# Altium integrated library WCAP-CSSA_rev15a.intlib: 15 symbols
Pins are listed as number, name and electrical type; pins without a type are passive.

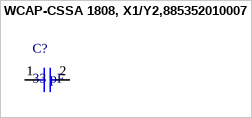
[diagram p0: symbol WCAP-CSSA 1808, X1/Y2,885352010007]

## WCAP-CSSA 1808, X1/Y2,885352010007
designator C?, comment 33 pF
WCAP-CSSA MLCC, NP0, 1808,X1/Y2, 33 pF,250Vac; Manufacturer: Wurth Elektronik; partNo: 885352010007; E-mail: libraries@we-online.com
footprint WCAP-CSSA 1808, H=1.4mm
pins: 1, 2


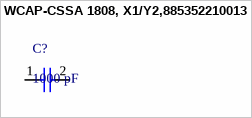
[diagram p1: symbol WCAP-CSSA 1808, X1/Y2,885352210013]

## WCAP-CSSA 1808, X1/Y2,885352210013
designator C?, comment 1000 pF
WCAP-CSSA MLCC, X7R, 1808,X1/Y2, 1000 pF,250Vac; Manufacturer: Wurth Elektronik; partNo: 885352210013; E-mail: libraries@we-online.com
footprint WCAP-CSSA 1808, H=2mm
pins: 1, 2


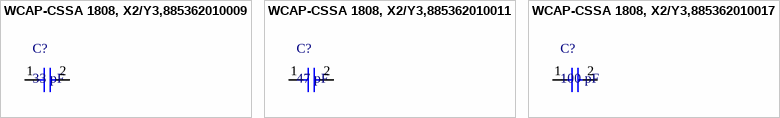
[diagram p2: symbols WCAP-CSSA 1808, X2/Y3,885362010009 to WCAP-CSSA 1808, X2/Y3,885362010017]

## WCAP-CSSA 1808, X2/Y3,885362010009
designator C?, comment 33 pF
WCAP-CSSA MLCC, NP0, 1808,X2/Y3, 33 pF,250Vac; Manufacturer: Wurth Elektronik; partNo: 885362010009; E-mail: libraries@we-online.com
footprint WCAP-CSSA 1808, H=1.4mm
pins: 1, 2

## WCAP-CSSA 1808, X2/Y3,885362010011
designator C?, comment 47 pF
WCAP-CSSA MLCC, NP0, 1808,X2/Y3, 47 pF,250Vac; Manufacturer: Wurth Elektronik; partNo: 885362010011; E-mail: libraries@we-online.com
footprint WCAP-CSSA 1808, H=1.6mm
pins: 1, 2

## WCAP-CSSA 1808, X2/Y3,885362010017
designator C?, comment 100 pF
WCAP-CSSA MLCC, NP0, 1808,X2/Y3, 100 pF,250Vac; Manufacturer: Wurth Elektronik; partNo: 885362010017; E-mail: libraries@we-online.com
footprint WCAP-CSSA 1808, H=2mm
pins: 1, 2


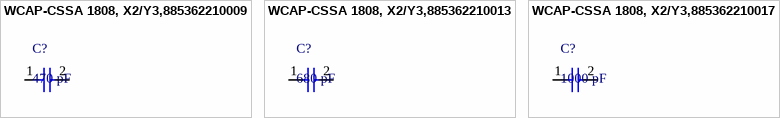
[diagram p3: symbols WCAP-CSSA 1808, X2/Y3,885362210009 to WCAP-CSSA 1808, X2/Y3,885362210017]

## WCAP-CSSA 1808, X2/Y3,885362210009
designator C?, comment 470 pF
WCAP-CSSA MLCC, X7R, 1808,X2/Y3, 470 pF,250Vac; Manufacturer: Wurth Elektronik; partNo: 885362210009; E-mail: libraries@we-online.com
footprint WCAP-CSSA 1808, H=1.6mm
pins: 1, 2

## WCAP-CSSA 1808, X2/Y3,885362210013
designator C?, comment 680 pF
WCAP-CSSA MLCC, X7R, 1808,X2/Y3, 680 pF,250Vac; Manufacturer: Wurth Elektronik; partNo: 885362210013; E-mail: libraries@we-online.com
footprint WCAP-CSSA 1808, H=1.6mm
pins: 1, 2

## WCAP-CSSA 1808, X2/Y3,885362210017
designator C?, comment 1000 pF
WCAP-CSSA MLCC, X7R, 1808,X2/Y3, 1000 pF,250Vac; Manufacturer: Wurth Elektronik; partNo: 885362210017; E-mail: libraries@we-online.com
footprint WCAP-CSSA 1808, H=2mm
pins: 1, 2


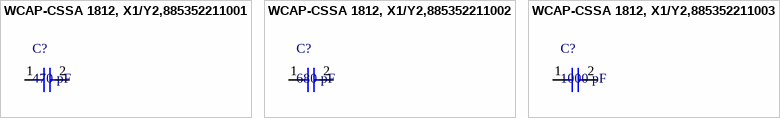
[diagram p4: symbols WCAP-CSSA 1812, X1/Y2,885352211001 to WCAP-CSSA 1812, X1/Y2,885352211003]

## WCAP-CSSA 1812, X1/Y2,885352211001
designator C?, comment 470 pF
WCAP-CSSA MLCC, X7R, 1812,X1/Y2, 470 pF,250Vac; Manufacturer: Wurth Elektronik; partNo: 885352211001; E-mail: libraries@we-online.com
footprint WCAP-CSSA 1812, H=1.6mm
pins: 1, 2

## WCAP-CSSA 1812, X1/Y2,885352211002
designator C?, comment 680 pF
WCAP-CSSA MLCC, X7R, 1812,X1/Y2, 680 pF,250Vac; Manufacturer: Wurth Elektronik; partNo: 885352211002; E-mail: libraries@we-online.com
footprint WCAP-CSSA 1812, H=2mm
pins: 1, 2

## WCAP-CSSA 1812, X1/Y2,885352211003
designator C?, comment 1000 pF
WCAP-CSSA MLCC, X7R, 1812,X1/Y2, 1000 pF,250Vac; Manufacturer: Wurth Elektronik; partNo: 885352211003; E-mail: libraries@we-online.com
footprint WCAP-CSSA 1812, H=2.5mm
pins: 1, 2


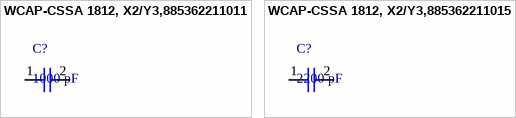
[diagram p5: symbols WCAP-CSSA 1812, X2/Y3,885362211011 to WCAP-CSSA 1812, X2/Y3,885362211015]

## WCAP-CSSA 1812, X2/Y3,885362211011
designator C?, comment 1000 pF
WCAP-CSSA MLCC, X7R, 1812,X2/Y3, 1000 pF,250Vac; Manufacturer: Wurth Elektronik; partNo: 885362211011; E-mail: libraries@we-online.com
footprint WCAP-CSSA 1812, H=1.6mm
pins: 1, 2

## WCAP-CSSA 1812, X2/Y3,885362211015
designator C?, comment 2200 pF
WCAP-CSSA MLCC, X7R, 1812,X2/Y3, 2200 pF,250Vac; Manufacturer: Wurth Elektronik; partNo: 885362211015; E-mail: libraries@we-online.com
footprint WCAP-CSSA 1812, H=2.5mm
pins: 1, 2


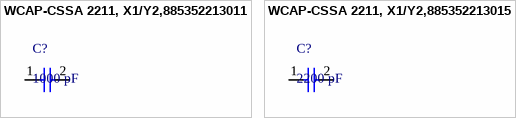
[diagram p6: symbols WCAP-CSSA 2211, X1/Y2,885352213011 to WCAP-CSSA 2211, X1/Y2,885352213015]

## WCAP-CSSA 2211, X1/Y2,885352213011
designator C?, comment 1000 pF
WCAP-CSSA MLCC, X7R, 2211,X1/Y2, 1000 pF,250Vac; Manufacturer: Wurth Elektronik; partNo: 885352213011; E-mail: libraries@we-online.com
footprint WCAP-CSSA 2211, H=2.5mm
pins: 1, 2

## WCAP-CSSA 2211, X1/Y2,885352213015
designator C?, comment 2200 pF
WCAP-CSSA MLCC, X7R, 2211,X1/Y2, 2200 pF,250Vac; Manufacturer: Wurth Elektronik; partNo: 885352213015; E-mail: libraries@we-online.com
footprint WCAP-CSSA 2211, H=2.5mm
pins: 1, 2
